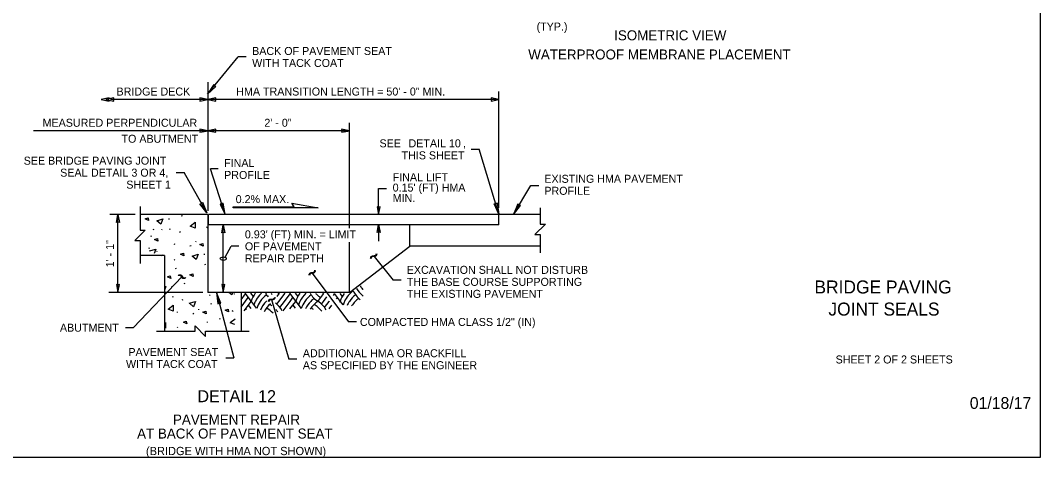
# Model space of a CAD drawing. Extents: x 99862 to 103151, y 100000 to 105076.
# Drawn here: x 101111 to 103151, y 102998 to 103874 of the extents above; entities that cross this region are included whole.
import ezdxf

# ---------------------------------------------------------------- set-up
doc = ezdxf.new("R2010")
doc.units = 0
for name, color, linetype in [('Level 1', 7, 'Continuous'), ('Level 15', 7, 'Continuous'), ('Level 16', 7, 'Continuous'), ('Level 20', 7, 'Continuous'), ('Level 27', 7, 'Continuous'), ('Level 62', 7, 'Continuous')]:
    doc.layers.add(name, color=color, linetype=linetype)

msp = doc.modelspace()

# ---------------------------------------------------------------- linework, layer by layer
at = {"layer": 'Level 1'}
msp.add_lwpolyline([(99862, 102999.5), (103151, 102999.5), (103151, 105075.5), (99862, 105075.5)], close=True, dxfattribs=at)
at = {"layer": 'Level 15'}
for p, q in [((101485.2, 103725.8), (101546.4, 103800.4)), ((101562.4, 103800.4), (101546.4, 103800.4)), ((102067.9, 103498.1), (102067.9, 103731.2)), ((101769.3, 103457.9), (101769.3, 103668.7)), ((102012.5, 103616), (102028.5, 103616)), ((102067.7, 103485.5), (102028.5, 103616)), ((101506.4, 103576.2), (101491.3, 103576.2)), ((101520.8, 103485.1), (101491.3, 103576.2)), ((101422.7, 103568.8), (101438.7, 103568.8)), ((101483.8, 103488.1), (101438.7, 103568.8)), ((101827.4, 103537.3), (101843.4, 103537.3)), ((101827.4, 103485.1), (101827.4, 103537.3)), ((102096.7, 103485.1), (102131.9, 103543.4)), ((102131.9, 103543.4), (102147.9, 103543.4)), ((101340.6, 103485.1), (101290.1, 103485.1)), ((101306.1, 103329.1), (101306.1, 103485.1)), ((101516.7, 103329.1), (101516.7, 103464.3)), ((101827.4, 103464.8), (101827.4, 103431.5)), ((101769.3, 103406.3), (101769.3, 103429.9)), ((101520.4, 103399.4), (101532.8, 103421.3)), ((101547.9, 103421.3), (101532.8, 103421.3)), ((101769.3, 103329), (101769.3, 103406.3)), ((101822.1, 103404.8), (101822.8, 103407.2)), ((101822.8, 103407.2), (101823.5, 103405.9)), ((101823.5, 103405.9), (101823.3, 103404.5)), ((101811.3, 103397.7), (101811.5, 103399)), ((101812, 103396.5), (101811.3, 103397.7)), ((101811.5, 103399), (101811.9, 103400.2)), ((101811.9, 103400.2), (101812.6, 103401.1)), ((101812.4, 103398.1), (101812, 103396.5)), ((101812.8, 103399.2), (101812.4, 103398.1)), ((101812.6, 103401.1), (101813.5, 103401.8)), ((101813.3, 103399.9), (101812.8, 103399.2)), ((101814, 103400.5), (101813.3, 103399.9)), ((101813.5, 103401.8), (101815.3, 103402.4)), ((101815.3, 103400.9), (101814, 103400.5)), ((101815.3, 103402.4), (101818.2, 103402.7)), ((101817, 103401), (101815.3, 103400.9)), ((101819.7, 103401.2), (101817, 103401)), ((101818.2, 103402.7), (101819.9, 103402.8)), ((101818.4, 103401.1), (101856.6, 103353.7)), ((101821.3, 103401.8), (101819.7, 103401.2)), ((101819.9, 103402.8), (101820.8, 103403.2)), ((101820.8, 103403.2), (101821.5, 103403.8)), ((101822.2, 103402.5), (101821.3, 103401.8)), ((101821.5, 103403.8), (101822.1, 103404.8)), ((101822.8, 103403.4), (101822.2, 103402.5)), ((101823.3, 103404.5), (101822.8, 103403.4)), ((101688.5, 103364), (101688.7, 103365.4)), ((101688.7, 103365.4), (101689.1, 103366.5)), ((101689.1, 103366.5), (101689.8, 103367.4)), ((101690, 103365.5), (101689.6, 103364.4)), ((101689.8, 103367.4), (101690.8, 103368.1)), ((101690.6, 103366.2), (101690, 103365.5)), ((101691.3, 103366.8), (101690.6, 103366.2)), ((101690.8, 103368.1), (101692.5, 103368.8)), ((101692.5, 103367.2), (101691.3, 103366.8)), ((101692.5, 103368.8), (101695.5, 103369)), ((101694.2, 103367.4), (101692.5, 103367.2)), ((101697, 103367.5), (101694.2, 103367.4)), ((101694.2, 103367.4), (101767.1, 103269.9)), ((101695.5, 103369), (101697.1, 103369.2)), ((101698.5, 103368.1), (101697, 103367.5)), ((101697.1, 103369.2), (101698, 103369.5)), ((101698, 103369.5), (101698.8, 103370.1)), ((101699.4, 103368.8), (101698.5, 103368.1)), ((101698.8, 103370.1), (101699.4, 103371.1)), ((101699.4, 103371.1), (101700, 103373.5)), ((101700.1, 103369.7), (101699.4, 103368.8)), ((101700, 103373.5), (101700.7, 103372.2)), ((101700.5, 103370.8), (101700.1, 103369.7)), ((101700.7, 103372.2), (101700.5, 103370.8)), ((101433.9, 103360.4), (101337.2, 103258.9)), ((101426.3, 103362.6), (101427, 103363.8)), ((101428.7, 103363.2), (101426.3, 103362.6)), ((101427, 103363.8), (101428.3, 103364.3)), ((101428.3, 103364.3), (101429.5, 103364.5)), ((101429.8, 103363.2), (101428.7, 103363.2)), ((101429.5, 103364.5), (101430.6, 103364.4)), ((101430.7, 103362.9), (101429.8, 103363.2)), ((101430.6, 103364.4), (101431.6, 103364)), ((101431.5, 103362.2), (101430.7, 103362.9)), ((101432.4, 103360.9), (101431.5, 103362.2)), ((101431.6, 103364), (101432.9, 103362.9)), ((101434.1, 103358.4), (101432.4, 103360.9)), ((101432.9, 103362.9), (101434.5, 103360.6)), ((101435.5, 103357.2), (101434.1, 103358.4)), ((101434.5, 103360.6), (101435.5, 103359.2)), ((101435.5, 103359.2), (101436.4, 103358.4)), ((101436.6, 103356.8), (101435.5, 103357.2)), ((101436.4, 103358.4), (101437.3, 103358)), ((101437.8, 103356.7), (101436.6, 103356.8)), ((101437.3, 103358), (101438.2, 103357.9)), ((101438.9, 103356.9), (101437.8, 103356.7)), ((101438.2, 103357.9), (101439.3, 103358.1)), ((101440.2, 103357.4), (101438.9, 103356.9)), ((101439.3, 103358.1), (101440.9, 103358.6)), ((101440.9, 103358.6), (101440.2, 103357.4)), ((101689.3, 103362.8), (101688.5, 103364)), ((101689.6, 103364.4), (101689.3, 103362.8)), ((101872.6, 103353.7), (101856.6, 103353.7)), ((101503.3, 103328.8), (101538.1, 103198.2)), ((101607.3, 103311.5), (101607.6, 103312.8)), ((101607.9, 103310.2), (101607.3, 103311.5)), ((101607.6, 103312.8), (101608.1, 103313.9)), ((101608.4, 103311.8), (101607.9, 103310.2)), ((101608.1, 103313.9), (101608.9, 103314.8)), ((101608.9, 103312.8), (101608.4, 103311.8)), ((101608.9, 103314.8), (101609.9, 103315.4)), ((101609.5, 103313.5), (101608.9, 103312.8)), ((101610.3, 103314), (101609.5, 103313.5)), ((101609.9, 103315.4), (101611.7, 103315.8)), ((101611.5, 103314.3), (101610.3, 103314)), ((101613.3, 103314.3), (101611.5, 103314.3)), ((101611.7, 103315.8), (101614.7, 103315.8)), ((101613.3, 103315.1), (101647.8, 103195.3)), ((101616, 103314.2), (101613.3, 103314.3)), ((101614.7, 103315.8), (101616.3, 103315.8)), ((101617.6, 103314.6), (101616, 103314.2)), ((101616.3, 103315.8), (101617.3, 103316)), ((101617.3, 103316), (101618.1, 103316.6)), ((101618.6, 103315.2), (101617.6, 103314.6)), ((101618.1, 103316.6), (101618.8, 103317.4)), ((101619.3, 103316), (101618.6, 103315.2)), ((101618.8, 103317.4), (101619.7, 103319.8)), ((101619.9, 103317.1), (101619.3, 103316)), ((101619.7, 103319.8), (101620.2, 103318.5)), ((101620.2, 103318.5), (101619.9, 103317.1)), ((101783.1, 103269.9), (101767.1, 103269.9)), ((101321.2, 103258.9), (101337.2, 103258.9)), ((101522.1, 103198.2), (101538.1, 103198.2)), ((101663.8, 103195.3), (101647.8, 103195.3))]:
    msp.add_line(p, q, dxfattribs=at)
for points in [[(101485.2, 103725.9), (101502.1, 103741.5), (101499.2, 103742.6), (101497.5, 103745.3)], [(101272.6, 103715.2), (101288.5, 103712.1), (101287.8, 103715.2), (101288.5, 103718.3)], [(101281.9, 103715.2), (101297.8, 103712.1), (101297.1, 103715.2), (101297.8, 103718.3)], [(101485.9, 103715.2), (101470, 103718.3), (101470.7, 103715.2), (101470, 103712.1)], [(101485.9, 103715.2), (101501.9, 103712.1), (101501.1, 103715.2), (101501.9, 103718.3)], [(102067.9, 103715.2), (102052.1, 103718.3), (102052.9, 103715.2), (102052.1, 103712.1)], [(101485.9, 103652.7), (101470, 103655.8), (101470.7, 103652.7), (101470, 103649.6)], [(101485.9, 103652.7), (101475.3, 103654.8), (101475.8, 103652.7), (101475.3, 103650.6)], [(101485.9, 103652.7), (101501.9, 103649.6), (101501.1, 103652.7), (101501.9, 103655.8)], [(101769.3, 103652.7), (101753.4, 103655.8), (101754.1, 103652.7), (101753.4, 103649.6)], [(101769.3, 103652.7), (101758.7, 103654.8), (101759.2, 103652.7), (101758.7, 103650.6)], [(101483.8, 103488.1), (101470, 103506.6), (101473.1, 103507.1), (101475.2, 103509.5)], [(101520.8, 103485.1), (101516.5, 103507.8), (101514, 103505.8), (101510.8, 103505.9)], [(102067.7, 103485.5), (102058.4, 103506.6), (102061.6, 103506.4), (102064.2, 103508.3)], [(101827.4, 103484.4), (101830.5, 103500.1), (101827.4, 103499.4), (101824.3, 103500.1)], [(102096.7, 103485.1), (102111, 103503.1), (102107.9, 103503.8), (102105.9, 103506.2)], [(101306.1, 103485.1), (101309.2, 103469.2), (101306.1, 103470), (101303, 103469.2)], [(101516.7, 103464.3), (101519.8, 103448.4), (101516.7, 103449.1), (101513.6, 103448.4)], [(101827.4, 103464.8), (101830.5, 103449.1), (101827.4, 103449.9), (101824.3, 103449.1)], [(101306.1, 103329.1), (101309.2, 103345), (101306.1, 103344.2), (101303, 103345)], [(101516.7, 103329.1), (101519.8, 103345), (101516.7, 103344.2), (101513.6, 103345)], [(101503.3, 103328.8), (101506.1, 103305.9), (101508.7, 103307.7), (101511.9, 103307.4)]]:
    msp.add_lwpolyline(points, close=True, dxfattribs=at)
for points in [[(101485.9, 103715.2), (101291.2, 103715.2)], [(102067.9, 103715.2), (101485.9, 103715.2)], [(101485.9, 103652.7), (101137, 103652.7)], [(101769.3, 103652.7), (101485.9, 103652.7)], [(101476, 103329), (101288, 103329)]]:
    msp.add_lwpolyline(points, dxfattribs=at)
msp.add_ellipse((101516.7, 103396.7), major_axis=(-6, 0), ratio=0.57735, dxfattribs=at)
at = {"layer": 'Level 16'}
for p, q in [((101408.1, 103476.8), (101407.8, 103475.3)), ((101432.8, 103482.4), (101434.9, 103483.1)), ((101376.6, 103455), (101378.7, 103455.8)), ((101394.1, 103455), (101392.9, 103453.4)), ((101409.3, 103455.7), (101411.4, 103456.5)), ((101428.9, 103449.9), (101431, 103450.7)), ((101484.7, 103460.1), (101483.4, 103458.5)), ((101889.9, 103421.7), (101889.9, 103464.3)), ((101372.1, 103441.6), (101374.1, 103442.4)), ((101418.9, 103426), (101418.6, 103424.5)), ((101461.7, 103431.3), (101461.4, 103429.7)), ((101367.9, 103417.4), (101369.9, 103418.2)), ((101383.7, 103411.9), (101383.4, 103410.3)), ((101450.1, 103422.1), (101452.2, 103422.9)), ((101478.8, 103406.1), (101478.5, 103404.5)), ((101419.7, 103395.1), (101418.5, 103393.5)), ((101480, 103385), (101482.1, 103385.8)), ((101421.2, 103377), (101423.2, 103377.8)), ((101438.6, 103346.7), (101440.6, 103347.5)), ((101413.9, 103341.1), (101413.5, 103339.6)), ((101490.4, 103324.4), (101489.2, 103322.8)), ((101415.1, 103320), (101417.1, 103320.8)), ((101434.7, 103314.2), (101436.7, 103315)), ((101491.9, 103306.3), (101493.9, 103307.1)), ((101424.6, 103290.3), (101424.3, 103288.8)), ((101455.9, 103286.4), (101457.9, 103287.2)), ((101467.4, 103295.6), (101467.1, 103294)), ((101484.6, 103270.4), (101484.2, 103268.9)), ((101509.3, 103276), (101511.3, 103276.8)), ((101539.8, 103264.9), (101530.3, 103268.4)), ((101530.6, 103268.8), (101540.4, 103276.2)), ((101425.4, 103259.4), (101424.2, 103257.8))]:
    msp.add_line(p, q, dxfattribs=at)
for points in [[(101360.6, 103476.2), (101366.4, 103478.2), (101367.2, 103472.7), (101360.6, 103476.2)], [(101383.9, 103472.6), (101396.1, 103476.4), (101392.1, 103465.7), (101384, 103472.5)], [(101450.3, 103461.6), (101460.5, 103469.4), (101460.4, 103457.9), (101450.5, 103461.5)], [(101379.3, 103435), (101385.1, 103437.1), (101385.9, 103431.6), (101379.3, 103435)], [(101470, 103425.2), (101475.8, 103427.2), (101476.6, 103421.7), (101470, 103425.2)], [(101369.5, 103412), (101381.8, 103415.8), (101378.5, 103407.1)], [(101431.3, 103405.5), (101437.1, 103407.5), (101437.9, 103402), (101431.3, 103405.5)], [(101454.6, 103401.9), (101466.8, 103405.7), (101462.8, 103395), (101454.8, 103401.8)], [(101393.5, 103402.8), (101395.6, 103404.4), (101395.5, 103402.8)], [(101450, 103364.3), (101455.8, 103366.4), (101456.6, 103360.9), (101450, 103364.3)], [(101405, 103360.2), (101410.8, 103362.2), (101411.6, 103356.7), (101405, 103360.2)], [(101399.1, 103339.9), (101401.9, 103340.7), (101399.1, 103333.4)], [(101535.2, 103329), (101533.5, 103324.3), (101528, 103329)], [(101448.8, 103307.3), (101461.1, 103311.1), (101457, 103300.4), (101449, 103307.2)], [(101406.4, 103295.5), (101416.6, 103303.2), (101416.4, 103291.8), (101406.6, 103295.4)], [(101475.7, 103289.5), (101481.5, 103291.5), (101482.3, 103286), (101475.7, 103289.5)], [(101520.7, 103293.6), (101526.5, 103295.6), (101527.3, 103290.1), (101520.7, 103293.6)], [(101399.1, 103267), (101401.3, 103268.7), (101401.1, 103257.3), (101399.1, 103258)], [(101437, 103269.8), (101442.8, 103271.8), (101443.6, 103266.3), (101437, 103269.8)]]:
    msp.add_lwpolyline(points, dxfattribs=at)
at = {"layer": 'Level 20'}
msp.add_lwpolyline([(101536.3, 103500.1), (101658.4, 103500.1), (101653.9, 103507.9), (101706.4, 103498.6), (101536.3, 103498.6)], close=True, dxfattribs=at)
at = {"layer": 'Level 27'}
for p, q in [((101485.5, 103749.8), (101485.5, 103492.1)), ((101485.5, 103485.1), (101350.4, 103485.1)), ((101485.5, 103485.1), (101485.5, 103329)), ((101487.4, 103464.3), (101487.4, 103485.1)), ((102067.9, 103485.1), (101487.4, 103485.1)), ((102067.9, 103464.3), (102067.9, 103485.2)), ((102150.2, 103485.1), (102067.9, 103485.1)), ((101769.3, 103464.3), (101485.5, 103464.3)), ((102067.9, 103464.3), (101769.3, 103464.3)), ((101769.3, 103329), (101889.9, 103421.7)), ((102150.2, 103421.7), (101889.9, 103421.7)), ((101399.1, 103402.8), (101350.4, 103402.8)), ((101399.1, 103402.8), (101399.1, 103251.5)), ((101769.3, 103329), (101485.5, 103329)), ((101552.5, 103329), (101552.5, 103251.5)), ((101552.6, 103314.5), (101561.2, 103326)), ((101560, 103327.6), (101572.4, 103311.1)), ((101571.2, 103327.6), (101576.4, 103320.6)), ((101624.3, 103320.9), (101629.2, 103327.4)), ((101628.1, 103311.1), (101640.3, 103327.4)), ((101639.2, 103311.1), (101650.3, 103326)), ((101649.3, 103327.4), (101661.5, 103311.1)), ((101660.4, 103327.4), (101665.5, 103320.6)), ((101706, 103311.1), (101718.1, 103327.2)), ((101729.2, 103327.1), (101729.2, 103327.2)), ((101736.9, 103322.6), (101739.4, 103326)), ((101738.6, 103327.2), (101750.6, 103311.1)), ((101749.7, 103327.1), (101754.6, 103320.6)), ((101552.4, 103299.3), (101566.8, 103318.6)), ((101558.4, 103292.5), (101572.4, 103311.1)), ((101566.8, 103303.7), (101572, 103296.8)), ((101572.4, 103311.1), (101582.5, 103297.6)), ((101623.9, 103305.6), (101628.1, 103311.1)), ((101630, 103298.9), (101639.2, 103311.1)), ((101636.4, 103292.5), (101650.3, 103311.1)), ((101650.1, 103295.9), (101661.5, 103311.1)), ((101650.3, 103311.1), (101655.9, 103318.6)), ((101655.9, 103303.7), (101660.6, 103297.5)), ((101661.5, 103311.1), (101672.3, 103296.7)), ((101713, 103305.6), (101717.2, 103311.1)), ((101717.2, 103311.1), (101724, 103320.2)), ((101719.1, 103298.9), (101728.3, 103311.1)), ((101728.3, 103311.1), (101728.9, 103312)), ((101728.3, 103296.3), (101733.9, 103303.7)), ((101743.1, 103316), (101745, 103318.6)), ((101749.2, 103309.3), (101750.6, 103311.1)), ((101750.6, 103311.1), (101756, 103303.9)), ((101561.2, 103296.3), (101562.8, 103294.2)), ((101650.3, 103296.3), (101650.5, 103296))]:
    msp.add_line(p, q, dxfattribs=at)
for points in [[(101350.4, 103501.1), (101350.4, 103453.9), (101360.8, 103453.9), (101339.9, 103433), (101350.4, 103433), (101350.4, 103386.8)], [(102150.2, 103498.6), (102150.2, 103466), (102160.7, 103466), (102139.8, 103445.1), (102150.2, 103445.1), (102150.2, 103408.2)], [(101383.1, 103251.5), (101460.4, 103251.5), (101460.4, 103261.9), (101481.3, 103241), (101481.3, 103251.5), (101568.5, 103251.5)]]:
    msp.add_lwpolyline(points, dxfattribs=at)
for centre, start, end in [((101570.4, 103372.8), 234.4943, 236.0964), ((101626.1, 103294.1), 143.5278, 162.3566), ((101631.7, 103286.6), 133.4791, 154.2266), ((101637.2, 103279.2), 127.1006, 145.4911), ((101648.4, 103357.9), 212.6507, 221.6129), ((101653.9, 103365.3), 222.3078, 226.037), ((101659.5, 103372.8), 233.5192, 236.0964), ((101715.2, 103294.1), 143.8044, 162.3566), ((101720.8, 103286.6), 133.8018, 154.2266), ((101726.3, 103279.2), 127.1006, 145.4911), ((101737.5, 103357.9), 212.9167, 236.0964), ((101743, 103365.3), 222.5035, 228.9599), ((101748.6, 103372.8), 233.8976, 236.0964), ((101804.3, 103294.1), 144.08, 162.3566), ((101809.9, 103286.6), 126.3063, 154.2266), ((101815.4, 103279.2), 127.1006, 145.4911), ((101826.6, 103357.9), 207.0135, 230.4491), ((101832.1, 103365.3), 210.023, 228.9599), ((101837.7, 103372.8), 213.0198, 220.9416), ((101837.7, 103372.8), 220.9415, 222.5143), ((101631.7, 103286.6), 154.2265, 162.3566), ((101637.2, 103279.2), 145.491, 161.557), ((101642.8, 103271.8), 135.7127, 157.1083), ((101648.4, 103264.4), 131.7594, 152.6729), ((101642.8, 103271.8), 134.3858, 135.7128), ((101579.9, 103256.9), 52.7144, 58.5465), ((101585.5, 103264.4), 29.427, 50.4977), ((101720.8, 103286.6), 154.2265, 162.3566), ((101726.3, 103279.2), 145.491, 161.9759), ((101731.9, 103271.8), 135.7127, 154.4664), ((101737.5, 103264.4), 123.9036, 146.5418), ((101731.9, 103271.8), 126.331, 135.7128), ((101669, 103256.9), 48.9597, 58.5465), ((101743, 103365.3), 228.9599, 236.0964), ((101674.6, 103264.4), 32.0851, 56.0963), ((101809.9, 103286.6), 154.2265, 162.2014), ((101815.4, 103279.2), 145.491, 155.055), ((101821, 103271.8), 135.7127, 147.5899), ((101821, 103271.8), 126.331, 135.7128), ((101832.1, 103365.3), 228.9599, 230.4471), ((101490.8, 103256.9), 36.3298, 38.8383), ((101574.4, 103249.5), 42.2669, 59.3021), ((101579.9, 103256.9), 35.7033, 41.8447), ((101663.5, 103249.5), 53.8167, 59.3021), ((101669, 103256.9), 37.6188, 48.9597)]:
    msp.add_arc(centre, 56.4, start, end, dxfattribs=at)

# ---------------------------------------------------------------- texts
at = {"layer": 'Level 15'}
msp.add_text('01/18/17', height=23.62, dxfattribs=at).set_placement((103009.4, 103095.8))
at = {"layer": 'Level 20'}
for s, height, p in [('(TYP.)', 16, (102143.2, 103853.3)), ('ISOMETRIC VIEW', 20, (102298.3, 103833.8)), ('BACK OF PAVEMENT SEAT', 16, (101574.4, 103804.4)), (' WATERPROOF MEMBRANE PLACEMENT', 20, (102119.1, 103795.4)), ('WITH TACK COAT', 16, (101574.4, 103780.4)), ('HMA TRANSITION LENGTH = 50\' - 0" MIN.', 16, (101542.7, 103723.2)), ('SEE ', 16, (101829.1, 103619.5)), ('DETAIL 10', 16, (101887.1, 103619.5)), ('THIS SHEET ', 16, (101873.2, 103595.5)), (',', 16, (101995.8, 103619.5)), ('SEE BRIDGE PAVING JOINT ', 16, (101117.6, 103584.8)), ('SEAL', 16, (101190.6, 103560.8)), (' DETAIL 3 OR 4,', 16, (101246.2, 103560.8)), ('SHEET 1', 16, (101322.8, 103536.8)), ('FINAL LIFT', 16, (101855.4, 103551.7)), ('EXISTING HMA PAVEMENT ', 16, (102158.7, 103548.5)), ("0.15' (FT) HMA ", 16, (101855.4, 103530.9)), ('PROFILE ', 16, (102158.7, 103524.5)), ('MIN.', 16, (101855.4, 103510.1)), ("0.93' (FT) MIN. = LIMIT", 16, (101559.9, 103437.3)), ('OF PAVEMENT ', 16, (101559.9, 103413.3)), ('REPAIR DEPTH', 16, (101559.9, 103389.3)), ('EXCAVATION SHALL NOT DISTURB ', 16, (101883.6, 103366.2)), ('THE BASE COURSE SUPPORTING ', 16, (101883.6, 103342.2)), ('THE EXISTING PAVEMENT', 16, (101883.6, 103318.2)), ('ABUTMENT', 16, (101190.1, 103250.4)), ('COMPACTED HMA CLASS 1/2" (IN)', 16, (101789.9, 103261.9)), ('PAVEMENT SEAT', 16, (101327, 103201.7)), ('ADDITIONAL HMA OR BACKFILL', 16, (101675.8, 103199.3)), ('WITH TACK COAT', 16, (101322.2, 103177.7)), ('AS SPECIFIED BY THE ENGINEER', 16, (101675.8, 103175.3)), ('DETAIL 12', 24, (101465.1, 103109.3)), ('PAVEMENT REPAIR', 20, (101416.1, 103064.5)), ('AT BACK OF PAVEMENT SEAT', 20, (101344.4, 103036.5)), ('(BRIDGE WITH HMA NOT SHOWN)', 16.5, (101362.1, 103003.3))]:
    msp.add_text(s, height=height, dxfattribs=at).set_placement(p)
for s, rotation, p in [('BRIDGE DECK', 360, (101303.2, 103723.2)), ('MEASURED PERPENDICULAR', 360, (101155.4, 103660.7)), ('2\' - 0" ', 360, (101598.8, 103660.7)), (' TO ABUTMENT', 360, (101307.3, 103628.7)), ('FINAL ', 360, (101518.4, 103580.2)), ('PROFILE', 360, (101518.4, 103556.2)), ('0.2% MAX.', 360, (101541.5, 103507.8)), ('1\' - 1"', 90.1816, (101298.2, 103379.3))]:
    msp.add_text(s, height=16, rotation=rotation, dxfattribs=at).set_placement(p)
at = {"layer": 'Level 62'}
for s, height, p in [('BRIDGE PAVING', 26, (102698.8, 103326.9)), ('JOINT SEALS', 26, (102726.7, 103282.7)), ('SHEET 2 OF 2 SHEETS', 16, (102741.1, 103186.8))]:
    msp.add_text(s, height=height, dxfattribs=at).set_placement(p)

doc.saveas('drawing.dxf')
